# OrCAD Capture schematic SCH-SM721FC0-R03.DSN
size A2; title: SM721FC0-R03
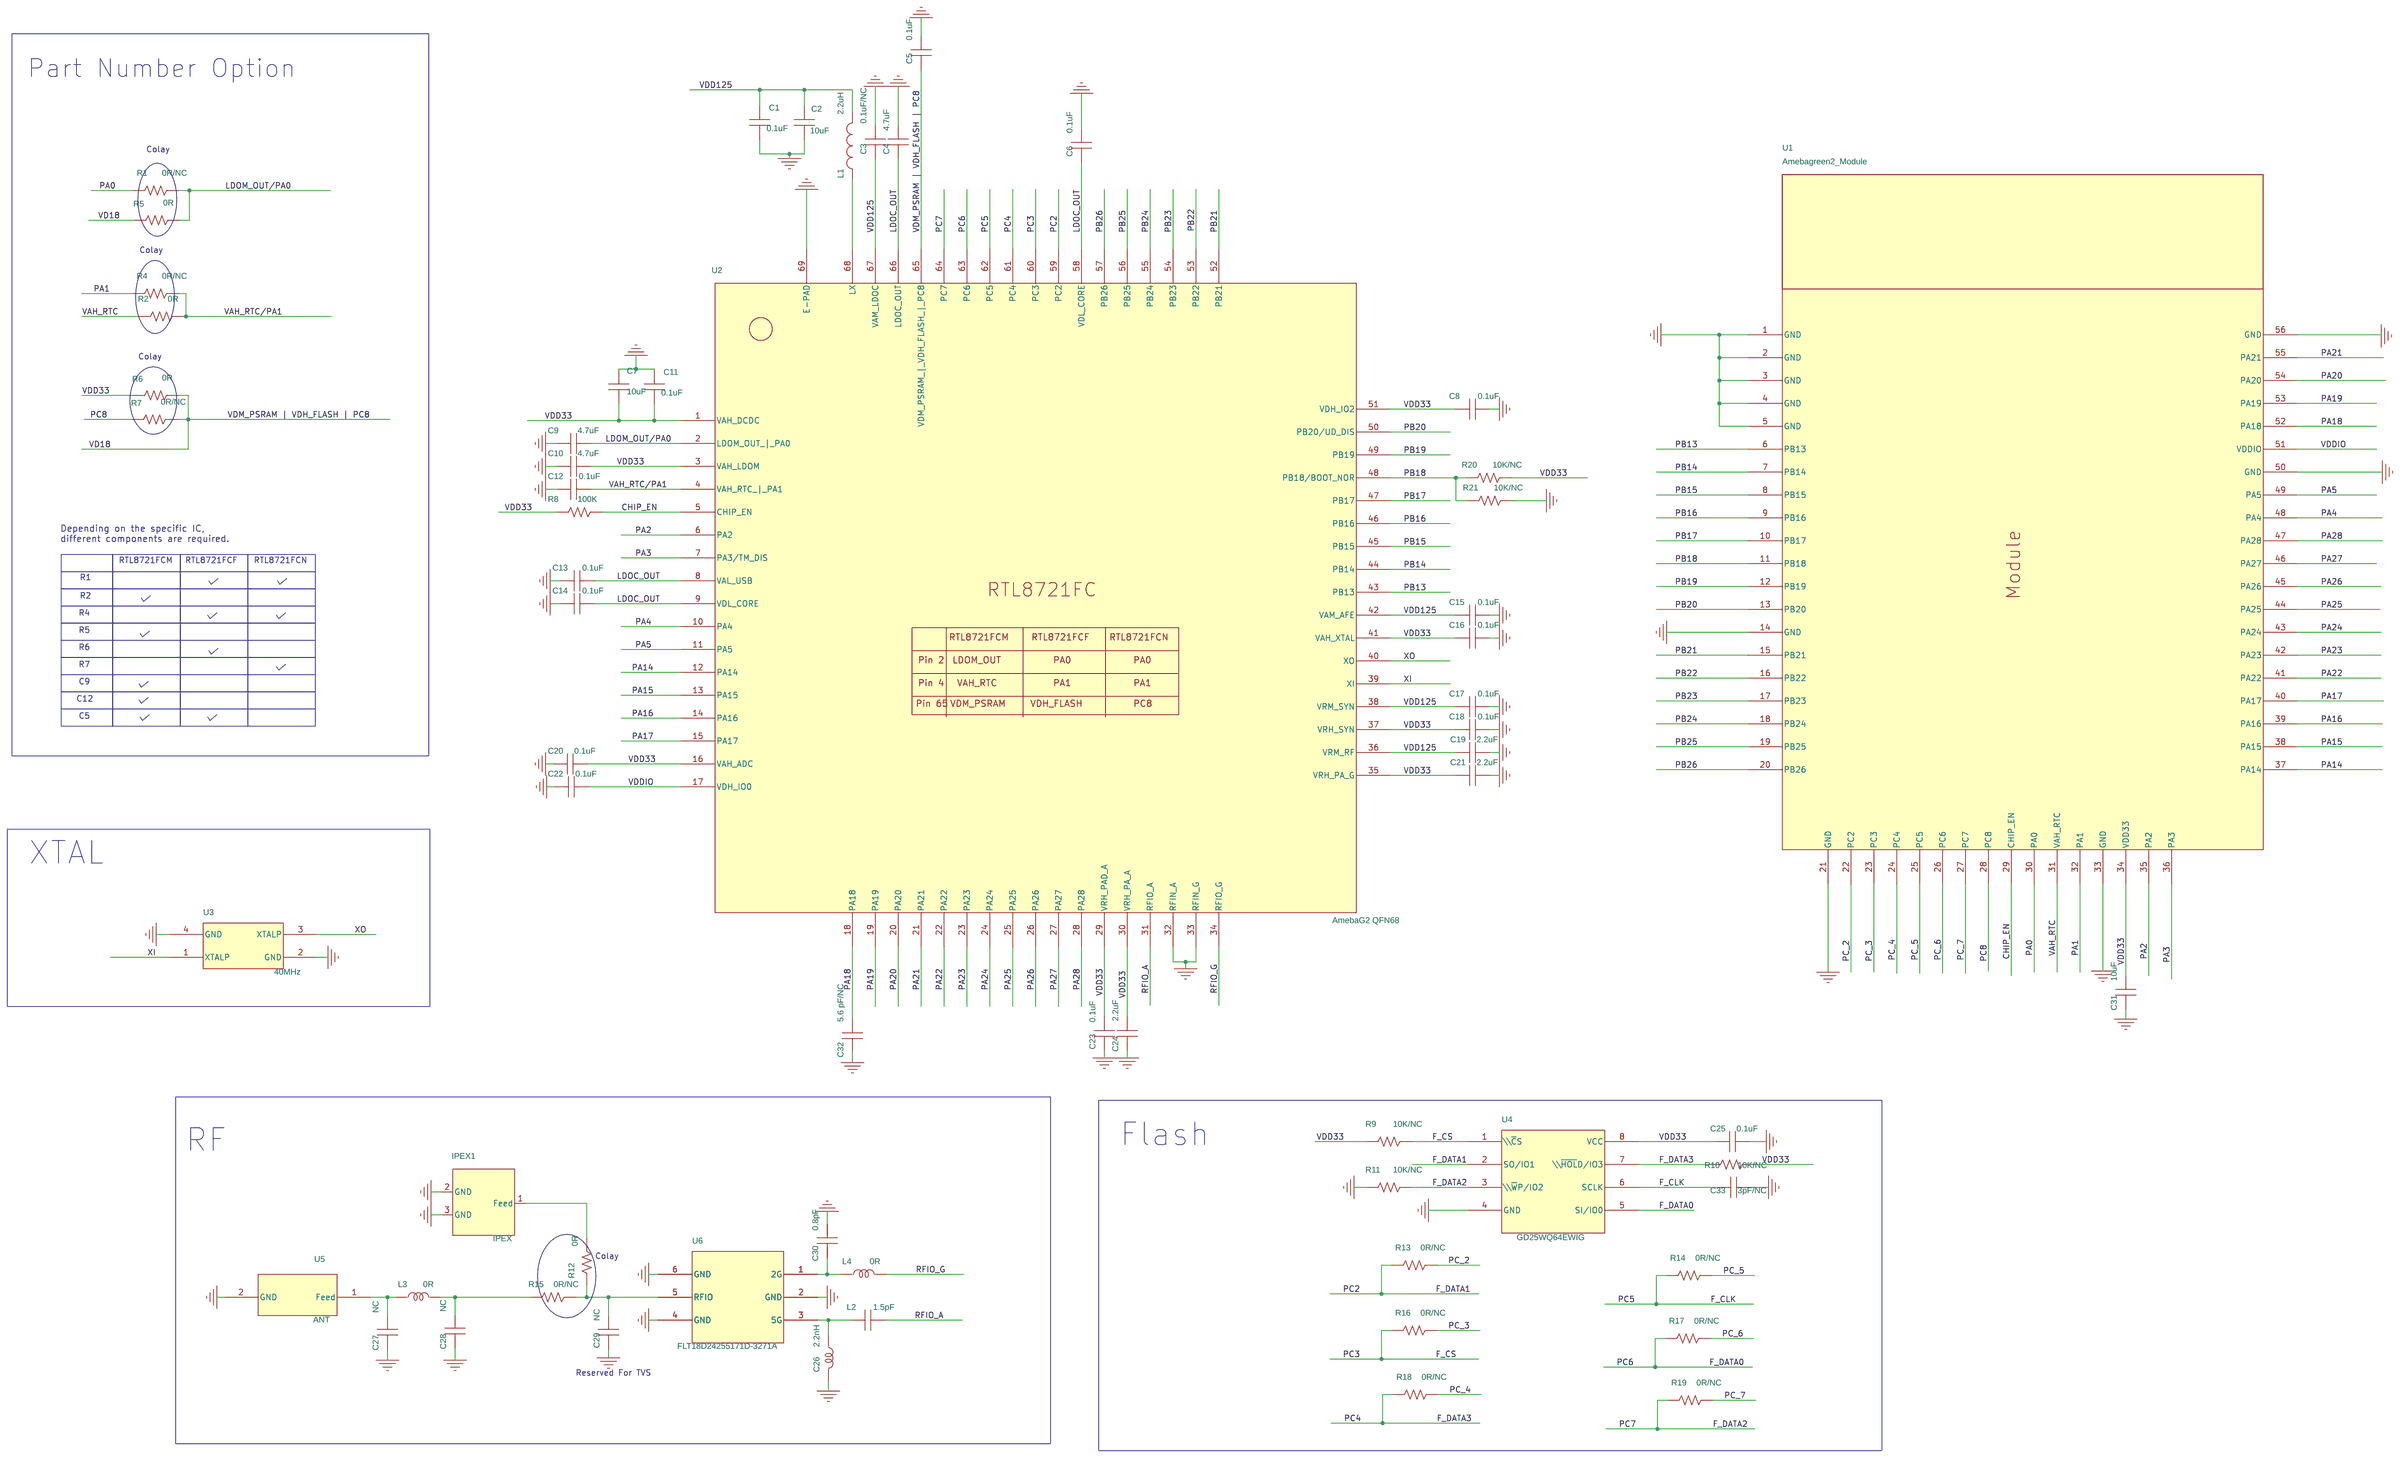
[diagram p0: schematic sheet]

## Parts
C1  0.1uF  [C0201]
C2  10uF  [C0402]
C3  0.1uF/NC  [C0201]
C4  4.7uF  [C0402]
C5  0.1uF  [C0201]
C6  0.1uF  [C0201]
C7  10uF  [C0402]
C8  0.1uF  [C0201]
C9  4.7uF  [C0402]
C10  4.7uF  [C0402]
C11  0.1uF  [C0201]
C12  0.1uF  [C0201]
C13  0.1uF  [C0201]
C14  0.1uF  [C0201]
C15  0.1uF  [C0201]
C16  0.1uF  [C0201]
C17  0.1uF  [C0201]
C18  0.1uF  [C0201]
C19  2.2uF  [C0402]
C20  0.1uF  [C0201]
C21  2.2uF  [C0402]
C22  0.1uF  [C0201]
C23  0.1uF  [C0201]
C24  2.2uF  [C0402]
C25  0.1uF  [C0201]
C26  2.2nH  [L0201]
C27  NC  [C0201]
C28  NC  [C0201]
C29  NC  [C0201]
C30  0.8pF  [C0201]
C31  10uF  [C0402]
C32  5.6 pF/NC  [C0201]
C33  3pF/NC  [C0201]
IPEX1  IPEX  [IPEX3-1.35-0.7X2.2]
L1  2.2uH  [L2016]
L2  1.5pF  [C0201]
L3  0R  [L0201]
L4  0R  [L0201]
R1  0R/NC  [R0201]
R2  0R  [R0201]
R4  0R/NC  [R0201]
R5  0R  [R0201]
R6  0R  [R0201]
R7  0R/NC  [R0201]
R8  100K  [R0201]
R9  10K/NC  [R0201]
R10  10K/NC  [R0201]
R11  10K/NC  [R0201]
R12  0R  [R0201]
R13  0R/NC  [R0201]
R14  0R/NC  [R0201]
R15  0R/NC  [R0201]
R16  0R/NC  [R0201]
R17  0R/NC  [R0201]
R18  0R/NC  [R0201]
R19  0R/NC  [R0201]
R20  10K/NC  [R0201]
R21  10K/NC  [R0201]
U1  Amebagreen2_Module  [MODULE56-18X29]
U2  AmebaG2 QFN68  [QFN68DR-0.4-8X8-EP5.2]
U3  40MHz  [XTAL-2016]
U4  GD25WQ64EWIG  [SOIC8-1.27-150-0.6X1.4]
U5  ANT  [G2_PANT]
U6  FLT18D24255171D-3271A  [DPX1608-6-0.5-0.25X0.6]

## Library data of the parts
C1 C3 C5 C6 C8 C11-C18 C20 C22 C23 C25 C32 C33 = CAPACITOR_NON-POL_0: ±10%,25V,X5R; Manufacturer: WALSIN; Part Number: 0201X104K250CT; Voltage: 25V; Datasheet: \\172.29.17.1\cn\WLAN\WLAN2\boarddesignLIB\05_component_database\Datasheet\Capacitor\Capacitor_Walsin_MLCC.pdf
C2 C31 = CAPACITOR_NON-POL_0: ±20%,10V,X5R; Manufacturer: WALSIN; Part Number: 0402X106M100CT; Voltage: 10V; Datasheet: \\172.29.17.1\cn\WLAN\WLAN2\boarddesignLIB\53_component_database\Datasheet\Capacitor\Capacitor_Walsin_MLCC.pdf
C4 C9 C10 = CAPACITOR_NON-POL_0: ±20%,16V,X5R; Manufacturer: WALSIN; Part Number: 0402X475M160CT; Voltage: 16V; Datasheet: \\172.29.17.1\cn\WLAN\WLAN2\boarddesignLIB\147_component_database\Datasheet\Capacitor\Capacitor_Walsin_MLCC.pdf
C7 = CAPACITOR_NON-POL_0: ±10%,16V,X5R; Manufacturer: WALSIN; Part Number: 0402X106K160CT; Voltage: 16V; Datasheet: \\172.29.17.1\cn\WLAN\WLAN2\boarddesignLIB\54_component_database\Datasheet\Capacitor\Capacitor_Walsin_MLCC.pdf
C19 C21 C24 = CAPACITOR_NON-POL_0: ±10%,25V,X5R; Manufacturer: WALSIN; Part Number: 0402X225K250CT; Voltage: 25V; Datasheet: \\172.29.17.1\cn\WLAN\WLAN2\boarddesignLIB\93_component_database\Datasheet\Capacitor\Capacitor_Walsin_MLCC.pdf
C26 = Inductor_RF: ±0.3nH,4min; Manufacturer: TAIYO YUDEN; Part Number: HK06032N2S-T
C27-C29 = CAPACITOR_NON-POL_0: +/-0.1pF,25V,NPO,Y; Manufacturer: WALSIN; Part Number: RF03N1R2B250CT; Voltage: 25V; Datasheet: \\172.29.17.1\cn\WLAN\WLAN2\boarddesignLIB\31_component_database\Datasheet\Capacitor\Capacitor_Walsin_MLCC.pdf
C30 = CAPACITOR_NON-POL_0: ±0.1pF,25V,NPO,Y; Manufacturer: WALSIN; Part Number: RF03N0R8B250CT; Voltage: 25V; Datasheet: \\172.29.17.1\cn\WLAN\WLAN2\boarddesignLIB\24_component_database\Datasheet\Capacitor\Capacitor_Walsin_MLCC.pdf
IPEX1 = TP_0: IPEX大头，IPEX1; Manufacturer: Argosy; Part Number: RFCSR-N3300-TP40; Datasheet: \\172.29.17.1\cn\WLAN\WLAN2\boarddesignLIB\01_component_database\Datasheet\Connector\RF Connector_Argosy_RFCSR-N3300-TP40_APL_Realtek (2017-03-06).pdf
L1 = Inductor_Power: ±20%; Manufacturer: TAIYO YUDEN; Part Number: CKP20162R2M-T
L2 = CAPACITOR_NON-POL_0: +/-0.25pF,25V,NPO,Y; Manufacturer: WALSIN; Part Number: RF03N1R5C250CT; Voltage: 25V; Datasheet: \\172.29.17.1\cn\WLAN\WLAN2\boarddesignLIB\37_component_database\Datasheet\Capacitor\Capacitor_Walsin_MLCC.pdf
L3 = Inductor_RF: ±0.3nH,4min; Manufacturer: CHILISIN; Part Number: CLH0603T-1N0S-F
L4 = Inductor_RF: ±0.3nH,15min; Manufacturer: TAIYO YUDEN; Part Number: HKQ0603S1N1C-T
R1 R2 R4-R7 R12-R19 = RES_0: JUMPER; Manufacturer: WALSIN; Part Number: WR02X000PTL; Datasheet: \\172.29.17.1\cn\WLAN\WLAN2\boarddesignLIB\01_component_database\Datasheet\Resistor\Resistor_Walsin_chipR.pdf
R8 = RES_0: +/-1%; Manufacturer: WALSIN; Part Number: WR02X1003FAL; Datasheet: \\172.29.17.1\cn\WLAN\WLAN2\boarddesignLIB\01_component_database\Datasheet\Resistor\Resistor_Walsin_chipR.pdf
R9-R11 R20 R21 = RES_0: +/-1%; Manufacturer: WALSIN; Part Number: WR02X1002FAL; Datasheet: \\172.29.17.1\cn\WLAN\WLAN2\boarddesignLIB\01_component_database\Datasheet\Resistor\Resistor_Walsin_chipR.pdf
U1 = Amebagreen2_Module_11
U2 = RL7005_QFN68: RL7005 QFN68; Manufacturer: Realtek
U3 = XTAL_0: 9pF，24omhs，10ppm，-30-85度; Manufacturer: 加高; Part Number: X2C040000B91H-HPZ; Datasheet: \\172.29.17.1\cn\WLAN\WLAN2\boarddesignLIB\01_component_database\Datasheet\XTAL-Resonator\XTAL-40M_Harmony_X2C040000B91H-HPZ 2016 9pF.pdf
U4 = Flash_0: Used for Module; Part Number: GD25Q16C; Datasheet: \\172.29.17.1\cn\WLAN\WLAN2\boarddesignLIB\01_component_database\Datasheet\Memory\FLASH_GigaDevice_GD25Q16CTIG.pdf
U5 = ANT
U6 = DPX_1: Manufacturer: ACX; Part Number: DP1608-R2455DBR1; Datasheet: \\172.29.17.1\cn\WLAN\WLAN2\boarddesignLIB\01_component_database\Datasheet\RF Chip\DPX_ACX_DP1608-R2455DBR1_Preliminary_S-R00-N1823_1.pdf

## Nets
GND: C1.2 C2.2 C3.1 C4.1 C5.1 C6.1 C7.2 C8.1 C9.1 C10.1 C11.1 C12.1 C13.1 C14.1 C15.1 C16.1 C17.1 C18.1 C19.2 C20.1 C21.2 C22.1 C23.1 C24.1 C25.2 C26.2 C27.2 C28.2 C29.2 C30.1 C31.2 C32.1 C33.2 IPEX1.2(GND) IPEX1.3(GND) R11.1 R21.2 U1.1(GND) U1.2(GND) U1.3(GND) U1.4(GND) U1.5(GND) U1.14(GND) U1.21(GND) U1.33(GND) U1.50(GND) U1.56(GND) U2.32(RFIN_A) U2.33(RFIN_G) U2.69(E-PAD) U3.2(GND) U3.4(GND) U4.4(GND) U5.2(GND) U6.2(GND) U6.4(GND) U6.6(GND)
VDD33: C7.1 C8.2 C10.2 C11.2 C16.2 C18.2 C20.2 C21.1 C23.2 C24.2 C25.1 C31.1 R6.1 R8.1 R9.1 R10.2 R20.2 U1.34(VDD33) U2.1(VAH_DCDC) U2.3(VAH_LDOM) U2.16(VAH_ADC) U2.29(VRH_PAD_A) U2.30(VRH_PA_A) U2.35(VRH_PA_G) U2.37(VRH_SYN) U2.41(VAH_XTAL) U2.51(VDH_IO2) U4.8(VCC)
VDD125: C1.1 C2.1 C3.2 C15.2 C17.2 C19.1 L1.2 U2.36(VRM_RF) U2.38(VRM_SYN) U2.42(VAM_AFE) U2.67(VAM_LDOC)
VDDIO: C22.2 U1.51(VDDIO) U2.17(VDH_IO0)
CHIP_EN: R8.2 U1.29(CHIP_EN) U2.5(CHIP_EN)
F_CLK: C33.1 R14.1 U2.62(PC5) U4.6(SCLK)
F_CS: R9.2 R16.1 U2.60(PC3) U4.1(\\~{C}S)
F_DATA0: R17.1 U2.63(PC6) U4.5(SI/IO0)
F_DATA1: R13.1 U2.59(PC2) U4.2(SO/IO1)
F_DATA2: R11.2 R19.1 U2.64(PC7) U4.3(\\~{W}P/IO2)
F_DATA3: R10.1 R18.1 U2.61(PC4) U4.7(\\~{HOL}D/IO3)
LDOC_OUT: C4.2 C6.2 C13.2 C14.2 U2.8(VAL_USB) U2.9(VDL_CORE) U2.58(VDL_CORE) U2.66(LDOC_OUT)
LDOM_OUT/PA0: C9.2 R1.2 R5.2 U2.2(LDOM_OUT_|_PA0)
PA0: R1.1 U1.30(PA0)
PA1: R4.1 U1.32(PA1)
PA2: U1.35(PA2) U2.6(PA2)
PA3: U1.36(PA3) U2.7(PA3/TM_DIS)
PA4: U1.48(PA4) U2.10(PA4)
PA5: U1.49(PA5) U2.11(PA5)
PA14: U1.37(PA14) U2.12(PA14)
PA15: U1.38(PA15) U2.13(PA15)
PA16: U1.39(PA16) U2.14(PA16)
PA17: U1.40(PA17) U2.15(PA17)
PA18: C32.2 U1.52(PA18) U2.18(PA18)
PA19: U1.53(PA19) U2.19(PA19)
PA20: U1.54(PA20) U2.20(PA20)
PA21: U1.55(PA21) U2.21(PA21)
PA22: U1.41(PA22) U2.22(PA22)
PA23: U1.42(PA23) U2.23(PA23)
PA24: U1.43(PA24) U2.24(PA24)
PA25: U1.44(PA25) U2.25(PA25)
PA26: U1.45(PA26) U2.26(PA26)
PA27: U1.46(PA27) U2.27(PA27)
PA28: U1.47(PA28) U2.28(PA28)
PB13: U1.6(PB13) U2.43(PB13)
PB14: U1.7(PB14) U2.44(PB14)
PB15: U1.8(PB15) U2.45(PB15)
PB16: U1.9(PB16) U2.46(PB16)
PB17: U1.10(PB17) U2.47(PB17)
PB18: R20.1 R21.1 U1.11(PB18) U2.48(PB18/BOOT_NOR)
PB19: U1.12(PB19) U2.49(PB19)
PB20: U1.13(PB20) U2.50(PB20/UD_DIS)
PB21: U1.15(PB21) U2.52(PB21)
PB22: U1.16(PB22) U2.53(PB22)
PB23: U1.17(PB23) U2.54(PB23)
PB24: U1.18(PB24) U2.55(PB24)
PB25: U1.19(PB25) U2.56(PB25)
PB26: U1.20(PB26) U2.57(PB26)
PC8: R7.1 U1.28(PC8)
PC_2: R13.2 U1.22(PC2)
PC_3: R16.2 U1.23(PC3)
PC_4: R18.2 U1.24(PC4)
PC_5: R14.2 U1.25(PC5)
PC_6: R17.2 U1.26(PC6)
PC_7: R19.2 U1.27(PC7)
RFIO_A: L2.2 U2.31(RFIO_A)
RFIO_G: L4.2 U2.34(RFIO_G)
VAH_RTC: R2.1 U1.31(VAH_RTC)
VAH_RTC/PA1: C12.2 R2.2 R4.2 U2.4(VAH_RTC_|_PA1)
VD18: C5.2 R5.1 R6.2 R7.2 U2.65(VDM_PSRAM_|_VDH_FLASH_|_PC8)
XI: U2.39(XI) U3.1(XTALP)
XO: U2.40(XO) U3.3(XTALP)
N17265: C29.1 R12.1 R15.2 U6.5(RFIO)
N20599: IPEX1.1(Feed) R12.2
N20769: C27.1 L3.1 U5.1(Feed)
N20777: C28.1 L3.2 R15.1
N16457751: L1.1 U2.68(LX)
N16546400: C30.2 L4.1 U6.1(2G)
N16546768: C26.1 L2.1 U6.3(5G)

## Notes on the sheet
- Part Number Option
- Colay
- Colay
- Colay
- Depending on the specific IC,
  different components are required.
- RTL8721FCM
- RTL8721FCF
- RTL8721FCN
- R1
- R2
- R4
- R5
- R6
- R7
- C9
- C12
- C5
- XTAL
- Flash
- RF
- Colay
- Reserved For TVS
